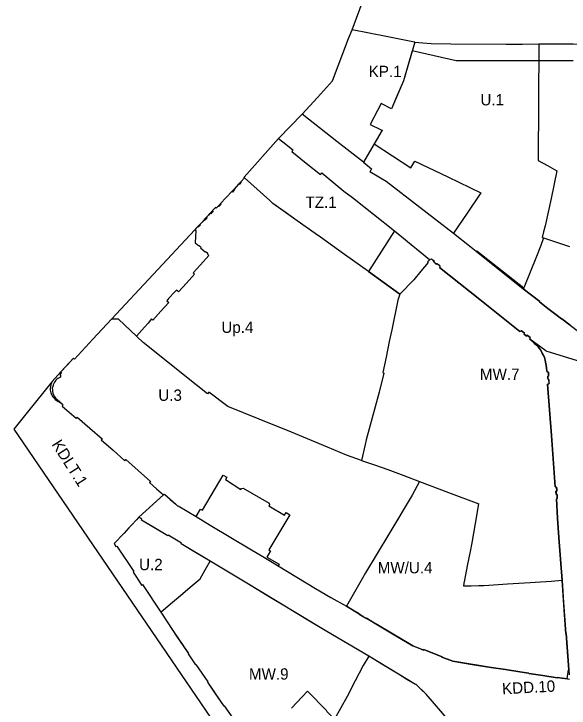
# Model space of a CAD drawing. Extents: x 7423893 to 7425332, y 5547241 to 5548246.
# Drawn here: x 7424259.3 to 7424503.9, y 5547447.3 to 5547753.2 of the extents above; entities that cross this region are included whole.
import ezdxf

# ---------------------------------------------------------------- set-up
doc = ezdxf.new("R2010")
doc.units = 0
for name, color, linetype in [('linie rozgraniczające', 7, 'Continuous'), ('nieprzekraczalne linie zabudowy', 7, 'Continuous'), ('obowiazujace linie zabudowy', 7, 'Continuous'), ('przeznaczenia terenów', 7, 'Continuous')]:
    doc.layers.add(name, color=color, linetype=linetype)

msp = doc.modelspace()

# ---------------------------------------------------------------- linework, layer by layer
at = {"layer": 'linie rozgraniczające'}
for p, q in [((7424408.27, 5547746.17), (7424415.24, 5547764.95)), ((7424375.95, 5547698.34), (7424386.38, 5547709.01)), ((7424493.58, 5547604.76), (7424486.55, 5547609.94)), ((7424493.58, 5547604.76), (7424511.39, 5547599.26)), ((7424314.36, 5547531.4), (7424325.23, 5547541.28))]:
    msp.add_line(p, q, dxfattribs=at)
for points in [[(7424386.38, 5547709.01), (7424393.03, 5547716.36), (7424399.68, 5547723.71), (7424406.67, 5547742.28), (7424408.27, 5547746.17)], [(7424435.91, 5547740.78), (7424435.82, 5547740.79), (7424423.38, 5547743.16), (7424415.83, 5547744.67), (7424408.27, 5547746.17)], [(7424435.91, 5547740.78), (7424430.91, 5547723.71), (7424425.66, 5547711.3), (7424421.07, 5547713.7), (7424416.27, 5547704.45), (7424421.12, 5547702.15), (7424421.56, 5547701.91), (7424418.02, 5547695.91), (7424413.27, 5547687.86)], [(7424435.91, 5547740.78), (7424439.45, 5547740.45), (7424443.07, 5547740.1), (7424451.8, 5547740.04), (7424476.21, 5547739.85), (7424483.4, 5547739.9), (7424490.59, 5547739.94)], [(7424490.59, 5547739.94), (7424490.42, 5547714.29), (7424490.26, 5547688.65), (7424494.37, 5547686.33), (7424498.48, 5547684.02), (7424495.92, 5547671.91), (7424493.35, 5547659.8), (7424492.67, 5547657.25), (7424491.99, 5547654.7), (7424492.63, 5547654.49), (7424491.39, 5547651.15), (7424489.49, 5547646.29), (7424486.69, 5547639.39), (7424483.89, 5547632.49), (7424483.68, 5547632.11)], [(7424490.59, 5547739.94), (7424499.64, 5547739.99), (7424504.2, 5547740.03), (7424505.66, 5547740.03), (7424514.71, 5547739.84), (7424523.77, 5547739.65), (7424523.77, 5547739.49), (7424523.77, 5547739.32), (7424527.77, 5547739.17), (7424533.17, 5547738.96), (7424542.57, 5547738.6), (7424545.24, 5547738.51), (7424545.32, 5547738.65), (7424547.84, 5547738.58), (7424550.37, 5547738.51), (7424550.36, 5547738.36), (7424553.12, 5547738.28), (7424554.49, 5547738.27), (7424555.25, 5547738.27), (7424559.28, 5547738.17), (7424567.07, 5547737.89), (7424578.1, 5547737.49)], [(7424413.27, 5547687.86), (7424401.65, 5547697), (7424386.38, 5547709.01)], [(7424360.93, 5547681.02), (7424360.82, 5547681.12), (7424360.71, 5547681.21), (7424375.95, 5547698.34), (7424379.11, 5547695.83), (7424382.26, 5547693.31), (7424381.99, 5547692.97), (7424381.72, 5547692.63), (7424388.08, 5547687.5), (7424394.45, 5547682.38), (7424394.74, 5547682.75), (7424395.02, 5547683.11), (7424401.2, 5547677.99), (7424404.7, 5547675.13), (7424408.5, 5547672.34), (7424417.74, 5547664.95), (7424426.98, 5547657.55)], [(7424413.27, 5547687.86), (7424416.91, 5547685), (7424416.5, 5547684.38), (7424416.08, 5547683.75), (7424423.3, 5547679.54), (7424452.98, 5547656.56), (7424460.77, 5547650.37), (7424463.01, 5547648.59), (7424473.34, 5547640.35), (7424473.34, 5547640.35), (7424483.68, 5547632.11)], [(7424360.93, 5547681.02), (7424359.26, 5547679.24), (7424358.31, 5547678.17), (7424356.32, 5547676.03), (7424355.34, 5547674.94), (7424350.34, 5547669.61), (7424349.86, 5547669.06), (7424349.38, 5547668.51), (7424348.5, 5547667.62), (7424348.35, 5547667.76), (7424348.2, 5547667.91), (7424347.54, 5547667.24), (7424346.88, 5547666.57), (7424346.34, 5547665.97), (7424345.8, 5547665.37), (7424344.2, 5547663.59), (7424343.63, 5547662.98), (7424343.07, 5547662.37), (7424342.21, 5547661.44), (7424341.35, 5547660.5), (7424340.82, 5547659.98), (7424340.29, 5547659.46), (7424339.66, 5547658.78), (7424339.03, 5547658.09)], [(7424426.98, 5547657.55), (7424421.28, 5547648.62), (7424415.57, 5547639.68), (7424405, 5547647.25), (7424394.42, 5547654.81), (7424392.07, 5547656.4), (7424388.12, 5547659.21), (7424384.17, 5547662.02), (7424378.8, 5547665.83), (7424373.44, 5547669.64), (7424372.02, 5547670.93), (7424366.48, 5547675.97), (7424360.93, 5547681.02)], [(7424302.32, 5547618.65), (7424320.67, 5547638.37), (7424339.03, 5547658.09)], [(7424426.98, 5547657.55), (7424430.2, 5547655), (7424434.27, 5547651.66), (7424438.33, 5547648.34), (7424442.38, 5547645.02), (7424442.53, 5547644.91), (7424442.66, 5547645.05), (7424442.78, 5547645.2), (7424442.9, 5547645.1), (7424443.02, 5547645), (7424443.12, 5547645.12), (7424443.22, 5547645.25), (7424443.86, 5547644.73), (7424444.49, 5547644.21), (7424444.26, 5547643.93), (7424444.88, 5547643.41), (7424445.5, 5547642.89), (7424445.75, 5547643.2), (7424447.02, 5547642.18), (7424446.85, 5547641.95), (7424447.07, 5547641.76), (7424446.83, 5547641.44), (7424464.54, 5547627.34), (7424482.24, 5547613.24), (7424482.5, 5547613.54), (7424482.69, 5547613.38), (7424482.88, 5547613.59), (7424483.53, 5547613.07), (7424484.18, 5547612.55), (7424483.96, 5547612.22), (7424485.18, 5547611.28), (7424485.44, 5547611.59), (7424486.09, 5547611.08), (7424486.75, 5547610.58), (7424486.57, 5547610.31), (7424486.75, 5547610.18), (7424486.55, 5547609.94), (7424487.99, 5547608.77), (7424490.32, 5547606.45), (7424491.29, 5547605.17), (7424492.87, 5547602.21), (7424493.42, 5547600.66), (7424493.96, 5547597.46), (7424494.12, 5547595.6), (7424494.42, 5547595.62), (7424494.44, 5547595.35), (7424494.75, 5547595.37), (7424494.87, 5547593.65), (7424494.53, 5547593.63), (7424494.57, 5547592.84), (7424494.61, 5547592.06), (7424494.8, 5547592.07), (7424494.99, 5547592.08), (7424495.03, 5547591.23), (7424495.07, 5547590.37), (7424494.95, 5547590.37), (7424494.82, 5547590.36), (7424494.82, 5547590.24), (7424494.82, 5547590.12), (7424494.44, 5547590.11), (7424496.07, 5547567.5), (7424497.69, 5547544.89), (7424497.89, 5547544.9), (7424498.09, 5547544.91), (7424498.09, 5547544.78), (7424498.1, 5547544.64), (7424498.23, 5547544.65), (7424498.36, 5547544.66), (7424498.42, 5547543.82), (7424498.48, 5547542.97), (7424498.28, 5547542.96), (7424498.08, 5547542.96), (7424498.13, 5547542.2), (7424498.19, 5547541.44), (7424498.57, 5547541.46), (7424498.63, 5547540.61), (7424498.69, 5547539.76), (7424498.43, 5547539.73), (7424498.44, 5547539.61), (7424498.45, 5547539.49), (7424498.27, 5547539.48), (7424498.83, 5547531), (7424499.4, 5547522.53), (7424500.11, 5547513.01), (7424500.81, 5547503.5), (7424501.48, 5547493.82), (7424502.14, 5547484.14), (7424502.3, 5547482.2), (7424502.47, 5547480.26), (7424502.61, 5547480.27), (7424503.17, 5547472.25), (7424503.74, 5547464.22), (7424503.9, 5547462.07)], [(7424492.63, 5547654.49), (7424504.02, 5547650.7)], [(7424415.57, 5547639.68), (7424422.42, 5547634.71), (7424429.26, 5547629.74), (7424428.49, 5547627.04), (7424425.76, 5547614.04), (7424424.67, 5547608.82), (7424423.25, 5547602.03), (7424421.84, 5547595.23)], [(7424504.38, 5547616.08), (7424500.71, 5547618.9), (7424500.58, 5547618.78), (7424496.84, 5547621.65), (7424494.52, 5547623.46), (7424490.92, 5547626.31), (7424490.96, 5547626.38), (7424491, 5547626.44), (7424483.68, 5547632.11)], [(7424302.32, 5547618.65), (7424294.17, 5547609.83), (7424286.03, 5547601.02), (7424285.78, 5547601.25), (7424285.53, 5547601.48), (7424279.94, 5547595.48), (7424276.22, 5547591.22), (7424275.82, 5547590.45), (7424275.61, 5547589.75), (7424275.39, 5547589.06), (7424275.36, 5547588.23), (7424275.33, 5547587.39), (7424275.44, 5547586.84), (7424275.54, 5547586.3), (7424275.92, 5547585.49), (7424276.19, 5547584.99), (7424276.45, 5547584.48), (7424277.01, 5547583.87), (7424277.57, 5547583.25), (7424278.8, 5547582.48), (7424279.51, 5547582.08), (7424280.22, 5547581.68), (7424280.96, 5547580.77), (7424280.66, 5547580.43), (7424283.73, 5547577.73), (7424286.8, 5547575.03), (7424287.03, 5547575.29), (7424287.25, 5547575.54), (7424292.73, 5547570.73), (7424298.2, 5547565.91), (7424297.81, 5547565.47), (7424303, 5547560.92), (7424308.19, 5547556.36), (7424308.65, 5547556.88), (7424314.06, 5547552.01), (7424319.47, 5547547.14), (7424319.11, 5547546.68), (7424322.17, 5547543.98), (7424325.23, 5547541.28), (7424325.58, 5547541.65), (7424325.81, 5547541.45), (7424328.23, 5547539.32), (7424330.64, 5547537.19), (7424331.61, 5547536.38), (7424331.66, 5547536.46), (7424339.61, 5547531.74), (7424345.76, 5547527.88), (7424363.94, 5547517.09), (7424368.19, 5547514.58), (7424375.79, 5547510.06), (7424384, 5547505.04), (7424392.22, 5547500.01), (7424399, 5547496.11), (7424405.79, 5547492.21)], [(7424421.84, 5547595.23), (7424422.29, 5547594.93), (7424420.24, 5547586.57), (7424414.56, 5547565.47), (7424414.08, 5547563.46), (7424412.44, 5547556.48), (7424405.78, 5547558.79), (7424397.47, 5547562.26), (7424381.64, 5547568.88), (7424367.39, 5547574.64), (7424360.51, 5547577.42), (7424353.56, 5547580.22), (7424345.25, 5547586.54), (7424344.63, 5547585.83), (7424339.64, 5547589.81), (7424316.31, 5547608.43), (7424305.37, 5547618.76), (7424302.32, 5547618.65)], [(7424276.22, 5547591.22), (7424265.23, 5547577.55), (7424259.33, 5547570.21)], [(7424259.33, 5547570.21), (7424469.69, 5547261.72)], [(7424412.44, 5547556.48), (7424418.23, 5547554.46), (7424424.01, 5547552.45), (7424431.02, 5547549.79), (7424438.03, 5547547.12), (7424450.75, 5547542.29), (7424464.19, 5547537.31)], [(7424438.03, 5547547.12), (7424434.75, 5547541.18), (7424424.5, 5547524.05), (7424414.25, 5547506.93), (7424412.91, 5547504.59), (7424409.35, 5547498.4), (7424405.79, 5547492.21)], [(7424474.69, 5547501.8), (7424472.66, 5547501.65), (7424468.59, 5547501.34), (7424466.27, 5547501.25), (7424465.17, 5547501.21), (7424464.07, 5547501.18), (7424460.79, 5547501.13), (7424457.52, 5547501.09), (7424457.71, 5547502.42), (7424457.89, 5547503.76), (7424459.19, 5547510.09), (7424460.49, 5547516.42), (7424461.23, 5547520.18), (7424462.71, 5547528.75), (7424464.19, 5547537.31)], [(7424314.36, 5547531.4), (7424313.34, 5547530.26), (7424311.17, 5547528), (7424310.01, 5547526.74), (7424307.86, 5547524.48), (7424306.69, 5547523.22), (7424304.54, 5547520.96), (7424303.47, 5547519.84), (7424304.27, 5547518.62), (7424304.63, 5547518.74), (7424312.19, 5547507.47), (7424311.86, 5547507.26), (7424312.79, 5547505.86), (7424314.69, 5547503), (7424315.59, 5547501.48), (7424315.98, 5547501.74), (7424324.03, 5547489.55), (7424329.32, 5547481.57), (7424330.69, 5547479.51), (7424336.15, 5547471.58), (7424336.31, 5547471.35), (7424336.13, 5547471.22), (7424339.35, 5547466.49), (7424339.45, 5547466.56), (7424344.7, 5547458.86), (7424344.57, 5547458.78), (7424347.78, 5547454.07), (7424347.86, 5547453.95), (7424347.95, 5547453.82), (7424351.76, 5547448.23), (7424351.98, 5547448.38), (7424355.74, 5547442.87)], [(7424457.28, 5547434.51), (7424440.89, 5547453.46), (7424436.37, 5547457.91), (7424436.2, 5547457.74), (7424428.7, 5547462.32), (7424415.66, 5547470.19), (7424397.21, 5547481.13), (7424380.53, 5547491.04), (7424380.6, 5547491.14), (7424380.18, 5547491.4), (7424362.01, 5547502.37), (7424345.72, 5547512.08), (7424332.96, 5547519.71), (7424333.17, 5547520.05), (7424331.74, 5547520.9), (7424328.82, 5547522.68), (7424327.37, 5547523.55), (7424327.18, 5547523.21), (7424315.5, 5547530.22), (7424315.72, 5547530.58), (7424314.36, 5547531.4)], [(7424324.03, 5547489.55), (7424328.37, 5547493.25), (7424332.71, 5547496.95), (7424337.04, 5547500.64), (7424341.38, 5547504.34), (7424343.55, 5547508.21), (7424345.72, 5547512.08)], [(7424486.69, 5547502.6), (7424479.21, 5547502.12), (7424476.72, 5547501.96), (7424474.69, 5547501.8)], [(7424500.81, 5547503.5), (7424496.02, 5547503.19), (7424493.75, 5547503.05), (7424491.24, 5547502.89), (7424488.96, 5547502.74), (7424486.69, 5547502.6)], [(7424504.05, 5547459.92), (7424503.51, 5547460.05), (7424502.97, 5547460.19), (7424500.78, 5547460.55), (7424498.59, 5547460.91), (7424498.58, 5547460.83), (7424498.56, 5547460.74), (7424492.33, 5547461.65), (7424486.09, 5547462.55), (7424486.11, 5547462.72), (7424484.15, 5547463.04), (7424482.19, 5547463.36), (7424475.88, 5547464.3), (7424469.58, 5547465.25), (7424453.56, 5547467.84), (7424452.73, 5547467.97), (7424450.32, 5547468.92), (7424447.9, 5547469.86), (7424447.93, 5547469.93), (7424447.96, 5547470), (7424443.91, 5547471.55), (7424439.86, 5547473.11), (7424439.79, 5547472.94), (7424435.02, 5547474.79), (7424420.25, 5547483.6), (7424417.47, 5547485.27), (7424414.69, 5547486.94), (7424414.65, 5547486.87), (7424414.6, 5547486.79), (7424412.98, 5547487.77), (7424411.36, 5547488.75), (7424411.43, 5547488.87), (7424408.61, 5547490.54), (7424405.79, 5547492.21)], [(7424415.66, 5547470.19), (7424413.19, 5547466.17), (7424409.66, 5547459.31), (7424406.13, 5547452.45), (7424400.58, 5547442.44), (7424397.01, 5547445.97), (7424397.17, 5547446.22), (7424388.59, 5547454.83), (7424381.66, 5547447.26)]]:
    msp.add_lwpolyline(points, dxfattribs=at)
at = {"layer": 'nieprzekraczalne linie zabudowy'}
msp.add_line((7424505.68, 5547732.48), (7424454.11, 5547732.54), dxfattribs=at)
msp.add_lwpolyline([(7424435.5, 5547635.98), (7424429.26, 5547629.74), (7424422.42, 5547634.71), (7424415.57, 5547639.68), (7424405, 5547647.25), (7424394.42, 5547654.81), (7424392.07, 5547656.4), (7424384.17, 5547662.02), (7424377.89, 5547666.48), (7424373.44, 5547669.64), (7424372.02, 5547670.93), (7424366.48, 5547675.97), (7424360.93, 5547681.02)], dxfattribs=at)
at = {"layer": 'obowiazujace linie zabudowy'}
msp.add_line((7424345.17, 5547646.69), (7424341.47, 5547642.61), dxfattribs=at)
for points in [[(7424434.79, 5547736.96), (7424430.91, 5547723.71), (7424427.64, 5547715.99), (7424425.66, 5547711.3), (7424421.07, 5547713.7), (7424416.27, 5547704.45), (7424421.12, 5547702.15), (7424421.56, 5547701.91), (7424419.79, 5547698.91), (7424418.02, 5547695.91)], [(7424454.11, 5547732.54), (7424444.45, 5547734.75), (7424434.79, 5547736.96)], [(7424418.02, 5547695.91), (7424434.24, 5547685.44), (7424435.11, 5547686.9), (7424435.98, 5547688.36), (7424450.48, 5547681.35), (7424464.98, 5547674.34)], [(7424360.93, 5547681.02), (7424359.26, 5547679.24), (7424359.49, 5547679.01), (7424358.53, 5547677.97), (7424358.31, 5547678.17), (7424356.32, 5547676.03), (7424356.55, 5547675.83), (7424355.58, 5547674.72), (7424355.34, 5547674.94), (7424352.84, 5547672.28), (7424350.34, 5547669.61), (7424350.56, 5547669.42), (7424350.08, 5547668.85), (7424349.6, 5547668.28), (7424349.38, 5547668.51), (7424348.94, 5547668.07), (7424348.5, 5547667.62), (7424348.37, 5547667.74), (7424348.2, 5547667.91), (7424347.54, 5547667.24), (7424346.88, 5547666.57), (7424347, 5547666.47), (7424347.11, 5547666.37), (7424346.57, 5547665.76), (7424346.02, 5547665.16), (7424345.91, 5547665.26), (7424345.8, 5547665.37), (7424345, 5547664.48), (7424344.2, 5547663.59), (7424344.29, 5547663.5), (7424344.39, 5547663.41), (7424343.83, 5547662.8), (7424343.27, 5547662.19), (7424343.17, 5547662.28), (7424343.07, 5547662.37), (7424342.21, 5547661.44), (7424341.35, 5547660.5), (7424341.45, 5547660.41), (7424341.54, 5547660.31), (7424341.03, 5547659.78), (7424340.51, 5547659.25), (7424340.38, 5547659.37), (7424340.29, 5547659.46), (7424339.66, 5547658.78), (7424339.03, 5547658.09), (7424339.23, 5547657.92), (7424339.43, 5547657.75), (7424339.33, 5547655.06), (7424339.22, 5547652.37), (7424339.88, 5547651.73), (7424340.53, 5547651.09), (7424340.71, 5547651.29), (7424341.26, 5547650.79), (7424341.81, 5547650.28), (7424341.69, 5547650.15), (7424341.6, 5547650.06), (7424342.56, 5547649.18), (7424343.52, 5547648.3), (7424343.72, 5547648.52), (7424344.25, 5547648.03), (7424344.79, 5547647.53), (7424344.67, 5547647.4), (7424344.55, 5547647.27), (7424345.17, 5547646.69), (7424345.17, 5547646.69)], [(7424464.98, 5547674.34), (7424458.98, 5547665.45), (7424452.98, 5547656.56)], [(7424452.98, 5547656.56), (7424460.77, 5547650.37), (7424463.01, 5547648.59), (7424463.22, 5547648.88), (7424483.89, 5547632.49), (7424483.68, 5547632.11), (7424487.34, 5547629.28), (7424491, 5547626.44), (7424490.92, 5547626.31), (7424494.52, 5547623.46), (7424496.84, 5547621.65), (7424500.58, 5547618.78), (7424500.71, 5547618.9), (7424508.04, 5547613.27)], [(7424442.38, 5547645.02), (7424441.94, 5547644.46), (7424441.5, 5547643.91), (7424441.74, 5547643.73), (7424438.62, 5547639.86), (7424435.5, 5547635.98)], [(7424502.97, 5547460.19), (7424503.62, 5547464.21), (7424503.74, 5547464.22), (7424502.61, 5547480.27), (7424502.47, 5547480.26), (7424502.14, 5547484.14), (7424500.81, 5547503.5), (7424500.11, 5547513.01), (7424499.4, 5547522.53), (7424498.83, 5547531), (7424498.27, 5547539.48), (7424498.45, 5547539.49), (7424498.43, 5547539.73), (7424498.69, 5547539.76), (7424498.57, 5547541.46), (7424498.19, 5547541.44), (7424498.08, 5547542.96), (7424498.48, 5547542.97), (7424498.36, 5547544.66), (7424498.1, 5547544.64), (7424498.09, 5547544.91), (7424497.69, 5547544.89), (7424496.07, 5547567.5), (7424494.44, 5547590.11), (7424494.82, 5547590.12), (7424494.82, 5547590.36), (7424495.07, 5547590.37), (7424494.99, 5547592.08), (7424494.61, 5547592.06), (7424494.57, 5547592.84), (7424494.56, 5547593.09), (7424494.53, 5547593.63), (7424494.87, 5547593.65), (7424494.75, 5547595.37), (7424494.44, 5547595.35), (7424494.42, 5547595.62), (7424494.12, 5547595.6), (7424493.96, 5547597.46), (7424493.69, 5547599.06), (7424493.42, 5547600.66), (7424493.15, 5547601.44), (7424492.87, 5547602.21), (7424492.08, 5547603.69), (7424491.29, 5547605.17), (7424490.8, 5547605.81), (7424490.32, 5547606.45), (7424489.16, 5547607.61), (7424487.99, 5547608.77), (7424487.27, 5547609.36), (7424486.55, 5547609.94), (7424486.75, 5547610.18), (7424486.57, 5547610.31), (7424486.75, 5547610.58), (7424486.09, 5547611.08), (7424485.44, 5547611.59), (7424485.18, 5547611.28), (7424484.57, 5547611.75), (7424483.96, 5547612.22), (7424484.1, 5547612.43), (7424484.18, 5547612.55), (7424483.53, 5547613.07), (7424482.88, 5547613.59), (7424482.78, 5547613.49), (7424482.69, 5547613.38), (7424482.59, 5547613.46), (7424482.5, 5547613.54), (7424482.37, 5547613.39), (7424482.24, 5547613.24), (7424464.54, 5547627.34), (7424446.83, 5547641.44), (7424446.95, 5547641.6), (7424447.07, 5547641.76), (7424446.96, 5547641.86), (7424446.85, 5547641.95), (7424446.94, 5547642.07), (7424447.02, 5547642.18), (7424446.38, 5547642.69), (7424445.75, 5547643.2), (7424445.62, 5547643.04), (7424445.5, 5547642.89), (7424444.88, 5547643.41), (7424444.26, 5547643.93), (7424444.37, 5547644.07), (7424444.49, 5547644.21), (7424443.86, 5547644.73), (7424443.22, 5547645.25), (7424443.11, 5547645.11), (7424443.02, 5547645), (7424442.78, 5547645.2), (7424442.66, 5547645.05), (7424442.53, 5547644.91), (7424442.38, 5547645.02)], [(7424341.47, 5547642.61), (7424341.47, 5547642.61), (7424339.88, 5547640.86), (7424338.29, 5547639.11), (7424338.62, 5547638.8), (7424338.96, 5547638.5), (7424335.43, 5547634.63), (7424331.9, 5547630.76), (7424331.46, 5547631.16), (7424331.02, 5547631.55), (7424330.54, 5547631.05), (7424330.05, 5547630.56), (7424327.62, 5547627.9), (7424326.76, 5547626.83), (7424327.54, 5547626.06), (7424324.06, 5547622.18), (7424320.58, 5547618.29), (7424320.29, 5547618.55), (7424320, 5547618.82), (7424318.41, 5547617.01), (7424316.82, 5547615.2), (7424313.34, 5547611.24)], [(7424313.34, 5547611.24), (7424305.37, 5547618.76), (7424303.84, 5547618.71), (7424302.32, 5547618.65), (7424294.17, 5547609.83), (7424286.03, 5547601.02), (7424285.78, 5547601.25), (7424285.53, 5547601.48), (7424282.74, 5547598.48), (7424279.94, 5547595.48), (7424280.11, 5547595.29), (7424280.28, 5547595.1), (7424279.91, 5547594.66), (7424279.53, 5547594.22), (7424279.81, 5547593.99), (7424279.83, 5547593.58), (7424279.84, 5547593.17), (7424279.29, 5547592.87), (7424278.74, 5547592.56), (7424278.29, 5547592.2), (7424277.85, 5547591.83), (7424277.5, 5547591.38), (7424277.15, 5547590.93), (7424276.89, 5547590.38), (7424276.63, 5547589.84), (7424276.45, 5547589.07), (7424276.26, 5547588.3), (7424276.29, 5547587.55), (7424276.32, 5547586.81), (7424276.54, 5547586.09), (7424276.77, 5547585.38), (7424277.09, 5547584.84), (7424277.42, 5547584.3), (7424277.88, 5547583.81), (7424278.34, 5547583.32), (7424278.74, 5547583.04), (7424279.14, 5547582.77), (7424280.22, 5547581.68), (7424280.96, 5547580.77), (7424280.66, 5547580.43)], [(7424280.66, 5547580.43), (7424286.8, 5547575.03), (7424287.25, 5547575.54), (7424292.73, 5547570.73), (7424298.2, 5547565.91), (7424298.01, 5547565.69), (7424297.81, 5547565.47), (7424303, 5547560.92), (7424308.19, 5547556.36), (7424308.42, 5547556.62), (7424308.65, 5547556.88), (7424314.06, 5547552.01), (7424319.47, 5547547.14), (7424319.29, 5547546.91), (7424319.11, 5547546.68), (7424322.17, 5547543.98), (7424325.23, 5547541.28), (7424325.58, 5547541.65), (7424325.81, 5547541.45), (7424330.64, 5547537.19), (7424331.12, 5547536.79), (7424331.61, 5547536.38), (7424331.66, 5547536.46), (7424335.63, 5547534.1), (7424339.61, 5547531.74), (7424339.61, 5547531.74), (7424341.55, 5547535.02), (7424342.35, 5547534.55), (7424351.58, 5547549.94), (7424353.1, 5547549.03), (7424352.48, 5547548.01), (7424359.33, 5547543.68), (7424359.62, 5547544.15), (7424360.28, 5547544.3), (7424371.73, 5547537.61), (7424371.9, 5547536.96), (7424371.64, 5547536.53), (7424378.58, 5547532.36), (7424379.28, 5547533.53), (7424380.87, 5547532.43), (7424371.66, 5547517.04), (7424372.4, 5547516.6), (7424370.79, 5547513.9), (7424376.17, 5547510.71), (7424375.79, 5547510.06), (7424384, 5547505.04), (7424392.22, 5547500.01), (7424399, 5547496.11), (7424405.79, 5547492.21)], [(7424449.08, 5547443.99), (7424440.89, 5547453.46), (7424438.63, 5547455.69), (7424436.37, 5547457.91), (7424436.2, 5547457.74), (7424432.45, 5547460.03), (7424428.7, 5547462.32), (7424422.18, 5547466.25), (7424415.66, 5547470.19), (7424406.44, 5547475.66), (7424397.21, 5547481.13), (7424388.87, 5547486.08), (7424380.53, 5547491.04), (7424380.59, 5547491.14), (7424380.18, 5547491.4), (7424371.09, 5547496.88), (7424362.01, 5547502.37), (7424353.87, 5547507.23), (7424345.72, 5547512.08), (7424339.34, 5547515.9), (7424332.96, 5547519.71), (7424333.17, 5547520.05), (7424332.46, 5547520.48), (7424331.74, 5547520.9), (7424328.82, 5547522.68), (7424328.09, 5547523.12), (7424327.37, 5547523.55), (7424327.18, 5547523.21), (7424321.34, 5547526.71), (7424315.5, 5547530.22), (7424315.72, 5547530.58), (7424314.36, 5547531.4), (7424313.34, 5547530.26), (7424311.17, 5547528), (7424310.01, 5547526.74), (7424307.86, 5547524.48), (7424306.69, 5547523.22), (7424304.54, 5547520.96), (7424303.47, 5547519.84), (7424304.27, 5547518.62), (7424304.63, 5547518.74), (7424312.19, 5547507.47), (7424311.86, 5547507.26), (7424312.79, 5547505.86), (7424314.69, 5547503), (7424315.59, 5547501.48), (7424315.98, 5547501.74), (7424324.03, 5547489.55), (7424329.32, 5547481.57), (7424336.31, 5547471.35), (7424336.13, 5547471.22), (7424339.35, 5547466.49), (7424339.45, 5547466.56), (7424344.7, 5547458.86), (7424344.55, 5547458.77), (7424347.86, 5547453.95), (7424351.76, 5547448.23), (7424351.98, 5547448.38), (7424355.74, 5547442.87)], [(7424405.79, 5547492.21), (7424411.43, 5547488.87), (7424411.36, 5547488.75), (7424414.6, 5547486.79), (7424414.69, 5547486.94), (7424420.25, 5547483.6), (7424427.64, 5547479.2), (7424435.02, 5547474.79), (7424437.41, 5547473.87), (7424439.79, 5547472.94), (7424439.86, 5547473.1), (7424443.91, 5547471.55), (7424447.96, 5547470), (7424447.9, 5547469.86), (7424452.73, 5547467.97), (7424461.16, 5547466.61), (7424469.58, 5547465.25), (7424475.88, 5547464.3), (7424482.19, 5547463.36), (7424484.15, 5547463.04), (7424486.11, 5547462.72), (7424486.09, 5547462.55), (7424492.33, 5547461.65), (7424498.56, 5547460.74), (7424498.59, 5547460.91), (7424500.78, 5547460.55), (7424502.97, 5547460.19)]]:
    msp.add_lwpolyline(points, dxfattribs=at)

# ---------------------------------------------------------------- texts
at = {"layer": 'przeznaczenia terenów'}
for s, p in [('KP.1', (7424415.61, 5547725.35)), ('U.1', (7424464.84, 5547712.88)), ('TZ.1', (7424387.79, 5547667.74)), ('Up.4', (7424350.72, 5547612.64)), ('MW.7', (7424464.6, 5547591.95)), ('U.3', (7424322.94, 5547582.72)), ('U.2', (7424314.46, 5547508.12)), ('MW/U.4', (7424419.59, 5547506.72)), ('MW.9', (7424362.86, 5547459.89))]:
    msp.add_text(s, height=5, dxfattribs=at).set_placement(p)
for s, rotation, p in [('KDLT.1', 302.5125, (7424275.78, 5547563.57)), ('KDD.10', 2.9844, (7424474.48, 5547453.41))]:
    msp.add_text(s, height=5, rotation=rotation, dxfattribs=at).set_placement(p)

doc.saveas('drawing.dxf')
